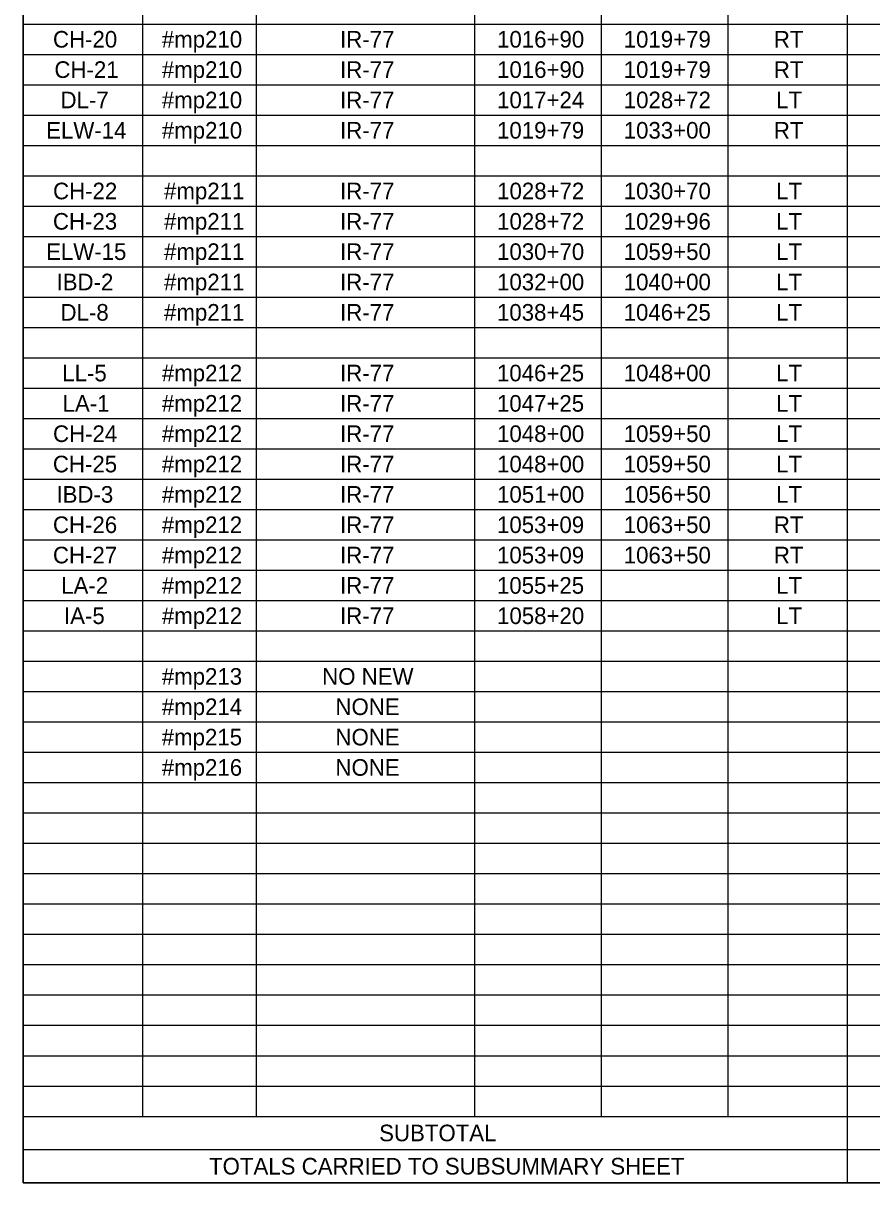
# Model space of a CAD drawing. Extents: x 91011267 to 91022583, y 37007614 to 37014266.
# Drawn here: x 91011277 to 91011662, y 37007614 to 37008139 of the extents above; entities that cross this region are included whole.
import ezdxf

# ---------------------------------------------------------------- set-up
doc = ezdxf.new("R2010")
doc.units = 0
doc.layers.add('SC_Scratch2', color=7, linetype='Continuous')
doc.layers.add('SH_Data', color=7, linetype='Continuous')

msp = doc.modelspace()

# ---------------------------------------------------------------- linework, layer by layer
at = {"layer": 'SC_Scratch2'}
msp.add_lwpolyline([(91011277.35, 37008663.81), (91012802.35, 37008663.81), (91012802.35, 37007613.81), (91011277.35, 37007613.81)], close=True, dxfattribs=at)
at = {"layer": 'SH_Data'}
for p, q in [((91011277.35, 37008289.61), (91011277.35, 37008083.53)), ((91011331.39, 37008289.61), (91011331.39, 37008083.53)), ((91011382.8, 37008289.61), (91011382.8, 37008083.53)), ((91011481.65, 37008289.61), (91011481.65, 37008083.53)), ((91011538.99, 37008289.61), (91011538.99, 37008083.53)), ((91011596.32, 37008289.61), (91011596.32, 37008083.53)), ((91011650.36, 37008289.61), (91011650.36, 37008083.53)), ((91011277.35, 37008138.48), (91011596.32, 37008138.48)), ((91011596.32, 37008138.48), (91011650.36, 37008138.48)), ((91011650.36, 37008138.48), (91011950.88, 37008138.48)), ((91011277.35, 37008124.75), (91011596.32, 37008124.75)), ((91011596.32, 37008124.75), (91011650.36, 37008124.75)), ((91011650.36, 37008124.75), (91011950.88, 37008124.75)), ((91011277.35, 37008111.01), (91011596.32, 37008111.01)), ((91011596.32, 37008111.01), (91011650.36, 37008111.01)), ((91011650.36, 37008111.01), (91011950.88, 37008111.01)), ((91011277.35, 37008097.27), (91011596.32, 37008097.27)), ((91011596.32, 37008097.27), (91011650.36, 37008097.27)), ((91011650.36, 37008097.27), (91011950.88, 37008097.27)), ((91011277.35, 37008083.53), (91011596.32, 37008083.53)), ((91011277.35, 37008083.53), (91011277.35, 37008069.79)), ((91011331.39, 37008083.53), (91011331.39, 37008069.79)), ((91011382.8, 37008083.53), (91011382.8, 37008069.79)), ((91011481.65, 37008083.53), (91011481.65, 37008069.79)), ((91011538.99, 37008083.53), (91011538.99, 37008069.79)), ((91011596.32, 37008083.53), (91011650.36, 37008083.53)), ((91011596.32, 37008083.53), (91011596.32, 37008069.79)), ((91011650.36, 37008083.53), (91011950.88, 37008083.53)), ((91011650.36, 37008083.53), (91011650.36, 37008069.79)), ((91011277.35, 37008069.79), (91011596.32, 37008069.79)), ((91011277.35, 37008069.79), (91011277.35, 37008056.05)), ((91011331.39, 37008069.79), (91011331.39, 37008056.05)), ((91011382.8, 37008069.79), (91011382.8, 37008056.05)), ((91011481.65, 37008069.79), (91011481.65, 37008056.05)), ((91011538.99, 37008069.79), (91011538.99, 37008056.05)), ((91011596.32, 37008069.79), (91011650.36, 37008069.79)), ((91011596.32, 37008069.79), (91011596.32, 37008056.05)), ((91011650.36, 37008069.79), (91011950.88, 37008069.79)), ((91011650.36, 37008069.79), (91011650.36, 37008056.05)), ((91011277.35, 37008056.05), (91011596.32, 37008056.05)), ((91011277.35, 37008056.05), (91011277.35, 37008014.84)), ((91011331.39, 37008056.05), (91011331.39, 37008014.84)), ((91011382.8, 37008056.05), (91011382.8, 37008014.84)), ((91011481.65, 37008056.05), (91011481.65, 37008014.84)), ((91011538.99, 37008056.05), (91011538.99, 37008014.84)), ((91011596.32, 37008056.05), (91011650.36, 37008056.05)), ((91011596.32, 37008056.05), (91011596.32, 37008014.84)), ((91011650.36, 37008056.05), (91011950.88, 37008056.05)), ((91011650.36, 37008056.05), (91011650.36, 37008014.84)), ((91011277.35, 37008042.32), (91011596.32, 37008042.32)), ((91011596.32, 37008042.32), (91011650.36, 37008042.32)), ((91011650.36, 37008042.32), (91011950.88, 37008042.32)), ((91011277.35, 37008028.58), (91011596.32, 37008028.58)), ((91011596.32, 37008028.58), (91011650.36, 37008028.58)), ((91011650.36, 37008028.58), (91011950.88, 37008028.58)), ((91011277.35, 37008014.84), (91011596.32, 37008014.84)), ((91011277.35, 37008014.84), (91011277.35, 37008001.1)), ((91011331.39, 37008014.84), (91011331.39, 37008001.1)), ((91011382.8, 37008014.84), (91011382.8, 37008001.1)), ((91011481.65, 37008014.84), (91011481.65, 37008001.1)), ((91011538.99, 37008014.84), (91011538.99, 37008001.1)), ((91011596.32, 37008014.84), (91011650.36, 37008014.84)), ((91011596.32, 37008014.84), (91011596.32, 37008001.1)), ((91011650.36, 37008014.84), (91011950.88, 37008014.84)), ((91011650.36, 37008014.84), (91011650.36, 37008001.1)), ((91011277.35, 37008001.1), (91011596.32, 37008001.1)), ((91011277.35, 37008001.1), (91011277.35, 37007987.36)), ((91011331.39, 37008001.1), (91011331.39, 37007987.36)), ((91011382.8, 37008001.1), (91011382.8, 37007987.36)), ((91011481.65, 37008001.1), (91011481.65, 37007987.36)), ((91011538.99, 37008001.1), (91011538.99, 37007987.36)), ((91011596.32, 37008001.1), (91011650.36, 37008001.1)), ((91011596.32, 37008001.1), (91011596.32, 37007987.36)), ((91011650.36, 37008001.1), (91011950.88, 37008001.1)), ((91011650.36, 37008001.1), (91011650.36, 37007987.36)), ((91011277.35, 37007987.36), (91011596.32, 37007987.36)), ((91011277.35, 37007987.36), (91011277.35, 37007946.15)), ((91011331.39, 37007987.36), (91011331.39, 37007946.15)), ((91011382.8, 37007987.36), (91011382.8, 37007946.15)), ((91011481.65, 37007987.36), (91011481.65, 37007946.15)), ((91011538.99, 37007987.36), (91011538.99, 37007946.15)), ((91011596.32, 37007987.36), (91011650.36, 37007987.36)), ((91011596.32, 37007987.36), (91011596.32, 37007946.15)), ((91011650.36, 37007987.36), (91011950.88, 37007987.36)), ((91011650.36, 37007987.36), (91011650.36, 37007946.15)), ((91011277.35, 37007973.62), (91011596.32, 37007973.62)), ((91011596.32, 37007973.62), (91011650.36, 37007973.62)), ((91011650.36, 37007973.62), (91011950.88, 37007973.62)), ((91011277.35, 37007959.89), (91011596.32, 37007959.89)), ((91011596.32, 37007959.89), (91011650.36, 37007959.89)), ((91011650.36, 37007959.89), (91011950.88, 37007959.89)), ((91011277.35, 37007946.15), (91011596.32, 37007946.15)), ((91011277.35, 37007946.15), (91011277.35, 37007932.41)), ((91011331.39, 37007946.15), (91011331.39, 37007932.41)), ((91011382.8, 37007946.15), (91011382.8, 37007932.41)), ((91011481.65, 37007946.15), (91011481.65, 37007932.41)), ((91011538.99, 37007946.15), (91011538.99, 37007932.41)), ((91011596.32, 37007946.15), (91011650.36, 37007946.15)), ((91011596.32, 37007946.15), (91011596.32, 37007932.41)), ((91011650.36, 37007946.15), (91011950.88, 37007946.15)), ((91011650.36, 37007946.15), (91011650.36, 37007932.41)), ((91011277.35, 37007932.41), (91011596.32, 37007932.41)), ((91011277.35, 37007932.41), (91011277.35, 37007918.67)), ((91011331.39, 37007932.41), (91011331.39, 37007918.67)), ((91011382.8, 37007932.41), (91011382.8, 37007918.67)), ((91011481.65, 37007932.41), (91011481.65, 37007918.67)), ((91011538.99, 37007932.41), (91011538.99, 37007918.67)), ((91011596.32, 37007932.41), (91011650.36, 37007932.41)), ((91011596.32, 37007932.41), (91011596.32, 37007918.67)), ((91011650.36, 37007932.41), (91011950.88, 37007932.41)), ((91011650.36, 37007932.41), (91011650.36, 37007918.67)), ((91011277.35, 37007918.67), (91011596.32, 37007918.67)), ((91011277.35, 37007918.67), (91011277.35, 37007613.81)), ((91011331.39, 37007918.67), (91011331.39, 37007643.9)), ((91011382.8, 37007918.67), (91011382.8, 37007643.9)), ((91011481.65, 37007918.67), (91011481.65, 37007643.9)), ((91011538.99, 37007918.67), (91011538.99, 37007643.9)), ((91011596.32, 37007918.67), (91011650.36, 37007918.67)), ((91011596.32, 37007918.67), (91011596.32, 37007643.9)), ((91011650.36, 37007918.67), (91011950.88, 37007918.67)), ((91011650.36, 37007918.67), (91011650.36, 37007613.81)), ((91011277.35, 37007904.93), (91011596.32, 37007904.93)), ((91011596.32, 37007904.93), (91011650.36, 37007904.93)), ((91011650.36, 37007904.93), (91011950.88, 37007904.93)), ((91011277.35, 37007891.19), (91011596.32, 37007891.19)), ((91011596.32, 37007891.19), (91011650.36, 37007891.19)), ((91011650.36, 37007891.19), (91011950.88, 37007891.19)), ((91011277.35, 37007877.46), (91011596.32, 37007877.46)), ((91011596.32, 37007877.46), (91011650.36, 37007877.46)), ((91011650.36, 37007877.46), (91011950.88, 37007877.46)), ((91011277.35, 37007863.72), (91011596.32, 37007863.72)), ((91011596.32, 37007863.72), (91011650.36, 37007863.72)), ((91011650.36, 37007863.72), (91011950.88, 37007863.72)), ((91011277.35, 37007849.98), (91011596.32, 37007849.98)), ((91011596.32, 37007849.98), (91011650.36, 37007849.98)), ((91011650.36, 37007849.98), (91011950.88, 37007849.98)), ((91011277.35, 37007836.24), (91011596.32, 37007836.24)), ((91011596.32, 37007836.24), (91011650.36, 37007836.24)), ((91011650.36, 37007836.24), (91011950.88, 37007836.24)), ((91011277.35, 37007822.5), (91011596.32, 37007822.5)), ((91011596.32, 37007822.5), (91011650.36, 37007822.5)), ((91011650.36, 37007822.5), (91011950.88, 37007822.5)), ((91011277.35, 37007808.76), (91011596.32, 37007808.76)), ((91011596.32, 37007808.76), (91011650.36, 37007808.76)), ((91011650.36, 37007808.76), (91011950.88, 37007808.76)), ((91011277.35, 37007795.03), (91011596.32, 37007795.03)), ((91011596.32, 37007795.03), (91011650.36, 37007795.03)), ((91011650.36, 37007795.03), (91011950.88, 37007795.03)), ((91011277.35, 37007781.29), (91011596.32, 37007781.29)), ((91011596.32, 37007781.29), (91011650.36, 37007781.29)), ((91011650.36, 37007781.29), (91011950.88, 37007781.29)), ((91011277.35, 37007767.55), (91011596.32, 37007767.55)), ((91011596.32, 37007767.55), (91011650.36, 37007767.55)), ((91011650.36, 37007767.55), (91011950.88, 37007767.55)), ((91011277.35, 37007753.81), (91011596.32, 37007753.81)), ((91011596.32, 37007753.81), (91011650.36, 37007753.81)), ((91011650.36, 37007753.81), (91011950.88, 37007753.81)), ((91011277.35, 37007740.07), (91011596.32, 37007740.07)), ((91011596.32, 37007740.07), (91011650.36, 37007740.07)), ((91011650.36, 37007740.07), (91011950.88, 37007740.07)), ((91011277.35, 37007726.33), (91011596.32, 37007726.33)), ((91011596.32, 37007726.33), (91011650.36, 37007726.33)), ((91011650.36, 37007726.33), (91011950.88, 37007726.33)), ((91011277.35, 37007712.6), (91011596.32, 37007712.6)), ((91011596.32, 37007712.6), (91011650.36, 37007712.6)), ((91011650.36, 37007712.6), (91011950.88, 37007712.6)), ((91011277.35, 37007698.86), (91011596.32, 37007698.86)), ((91011596.32, 37007698.86), (91011650.36, 37007698.86)), ((91011650.36, 37007698.86), (91011950.88, 37007698.86)), ((91011277.35, 37007685.12), (91011596.32, 37007685.12)), ((91011596.32, 37007685.12), (91011650.36, 37007685.12)), ((91011650.36, 37007685.12), (91011950.88, 37007685.12)), ((91011277.35, 37007671.38), (91011596.32, 37007671.38)), ((91011596.32, 37007671.38), (91011650.36, 37007671.38)), ((91011650.36, 37007671.38), (91011950.88, 37007671.38)), ((91011277.35, 37007657.64), (91011596.32, 37007657.64)), ((91011596.32, 37007657.64), (91011650.36, 37007657.64)), ((91011650.36, 37007657.64), (91011950.88, 37007657.64)), ((91011277.35, 37007643.9), (91011596.32, 37007643.9)), ((91011596.32, 37007643.9), (91011650.36, 37007643.9)), ((91011650.36, 37007643.9), (91011950.88, 37007643.9)), ((91011277.35, 37007628.86), (91011596.32, 37007628.86)), ((91011596.32, 37007628.86), (91011650.36, 37007628.86)), ((91011650.36, 37007628.86), (91011950.88, 37007628.86)), ((91011277.35, 37007613.81), (91011596.32, 37007613.81)), ((91011596.32, 37007613.81), (91011650.36, 37007613.81)), ((91011650.36, 37007613.81), (91011950.88, 37007613.81))]:
    msp.add_line(p, q, dxfattribs=at)

# ---------------------------------------------------------------- texts
for s, height, p in [('CH-20', 7.523, (91011290.83, 37008127.85)), ('#mp210', 7.523, (91011340.11, 37008127.85)), ('IR-77', 7.523, (91011420.79, 37008127.85)), ('1016+90', 7.523, (91011491.87, 37008127.85)), ('1019+79', 7.523, (91011549.19, 37008127.85)), ('RT', 7.523, (91011617.17, 37008127.85)), ('CH-21', 7.523, (91011291.48, 37008114.12)), ('#mp210', 7.523, (91011340.11, 37008114.12)), ('IR-77', 7.523, (91011420.79, 37008114.12)), ('1016+90', 7.523, (91011491.87, 37008114.12)), ('1019+79', 7.523, (91011549.19, 37008114.12)), ('RT', 7.523, (91011617.17, 37008114.12)), ('DL-7', 7.523, (91011294.26, 37008100.38)), ('#mp210', 7.523, (91011340.11, 37008100.38)), ('IR-77', 7.523, (91011420.79, 37008100.38)), ('1017+24', 7.523, (91011491.87, 37008100.38)), ('1028+72', 7.523, (91011549.23, 37008100.38)), ('LT', 7.523, (91011618.23, 37008100.38)), ('ELW-14', 7.523, (91011287.75, 37008086.64)), ('#mp210', 7.523, (91011340.11, 37008086.64)), ('IR-77', 7.523, (91011420.79, 37008086.64)), ('1019+79', 7.523, (91011491.85, 37008086.64)), ('1033+00', 7.523, (91011549.21, 37008086.64)), ('RT', 7.523, (91011617.17, 37008086.64)), ('CH-22', 7.523, (91011290.86, 37008059.16)), ('#mp211', 7.523, (91011341.11, 37008059.16)), ('IR-77', 7.523, (91011420.79, 37008059.16)), ('1028+72', 7.523, (91011491.9, 37008059.16)), ('1030+70', 7.523, (91011549.21, 37008059.16)), ('LT', 7.523, (91011618.23, 37008059.16)), ('CH-23', 7.523, (91011290.82, 37008045.42)), ('#mp211', 7.523, (91011341.11, 37008045.42)), ('IR-77', 7.523, (91011420.79, 37008045.42)), ('1028+72', 7.523, (91011491.9, 37008045.42)), ('1029+96', 7.523, (91011549.2, 37008045.42)), ('LT', 7.523, (91011618.23, 37008045.42)), ('ELW-15', 7.523, (91011287.71, 37008031.69)), ('#mp211', 7.523, (91011341.11, 37008031.69)), ('IR-77', 7.523, (91011420.79, 37008031.69)), ('1030+70', 7.523, (91011491.87, 37008031.69)), ('1059+50', 7.523, (91011549.21, 37008031.69)), ('LT', 7.523, (91011618.23, 37008031.69)), ('IBD-2', 7.523, (91011292.44, 37008017.95)), ('#mp211', 7.523, (91011341.11, 37008017.95)), ('IR-77', 7.523, (91011420.79, 37008017.95)), ('1032+00', 7.523, (91011491.87, 37008017.95)), ('1040+00', 7.523, (91011549.21, 37008017.95)), ('LT', 7.523, (91011618.23, 37008017.95)), ('DL-8', 7.523, (91011294.26, 37008004.21)), ('#mp211', 7.523, (91011341.11, 37008004.21)), ('IR-77', 7.523, (91011420.79, 37008004.21)), ('1038+45', 7.523, (91011491.83, 37008004.21)), ('1046+25', 7.523, (91011549.17, 37008004.21)), ('LT', 7.523, (91011618.23, 37008004.21)), ('LL-5', 7.523, (91011295.03, 37007976.73)), ('#mp212', 7.523, (91011340.13, 37007976.73)), ('IR-77', 7.523, (91011420.79, 37007976.73)), ('1046+25', 7.523, (91011491.83, 37007976.73)), ('1048+00', 7.523, (91011549.21, 37007976.73)), ('LT', 7.523, (91011618.23, 37007976.73)), ('LA-1', 7.523, (91011295.18, 37007962.99)), ('#mp212', 7.523, (91011340.13, 37007962.99)), ('IR-77', 7.523, (91011420.79, 37007962.99)), ('1047+25', 7.523, (91011491.83, 37007962.99)), ('LT', 7.523, (91011618.23, 37007962.99)), ('CH-24', 7.523, (91011290.84, 37007949.26)), ('#mp212', 7.523, (91011340.13, 37007949.26)), ('IR-77', 7.523, (91011420.79, 37007949.26)), ('1048+00', 7.523, (91011491.87, 37007949.26)), ('1059+50', 7.523, (91011549.21, 37007949.26)), ('LT', 7.523, (91011618.23, 37007949.26)), ('CH-25', 7.523, (91011290.79, 37007935.52)), ('#mp212', 7.523, (91011340.13, 37007935.52)), ('IR-77', 7.523, (91011420.79, 37007935.52)), ('1048+00', 7.523, (91011491.87, 37007935.52)), ('1059+50', 7.523, (91011549.21, 37007935.52)), ('LT', 7.523, (91011618.23, 37007935.52)), ('IBD-3', 7.523, (91011292.41, 37007921.78)), ('#mp212', 7.523, (91011340.13, 37007921.78)), ('IR-77', 7.523, (91011420.79, 37007921.78)), ('1051+00', 7.523, (91011491.87, 37007921.78)), ('1056+50', 7.523, (91011549.21, 37007921.78)), ('LT', 7.523, (91011618.23, 37007921.78)), ('CH-26', 7.523, (91011290.82, 37007908.04)), ('#mp212', 7.523, (91011340.13, 37007908.04)), ('IR-77', 7.523, (91011420.79, 37007908.04)), ('1053+09', 7.523, (91011491.85, 37007908.04)), ('1063+50', 7.523, (91011549.21, 37007908.04)), ('RT', 7.523, (91011617.17, 37007908.04)), ('CH-27', 7.523, (91011290.82, 37007894.3)), ('#mp212', 7.523, (91011340.13, 37007894.3)), ('IR-77', 7.523, (91011420.79, 37007894.3)), ('1053+09', 7.523, (91011491.85, 37007894.3)), ('1063+50', 7.523, (91011549.21, 37007894.3)), ('RT', 7.523, (91011617.17, 37007894.3)), ('LA-2', 7.523, (91011294.56, 37007880.56)), ('#mp212', 7.523, (91011340.13, 37007880.56)), ('IR-77', 7.523, (91011420.79, 37007880.56)), ('1055+25', 7.523, (91011491.83, 37007880.56)), ('LT', 7.523, (91011618.23, 37007880.56)), ('#mp212', 7.523, (91011340.13, 37007866.83)), ('1058+20', 7.523, (91011491.87, 37007866.83)), ('IA-5', 7.523, (91011295.82, 37007866.83)), ('IR-77', 7.523, (91011420.79, 37007866.83)), ('LT', 7.523, (91011618.23, 37007866.83)), ('#mp213', 7.523, (91011340.1, 37007839.35)), ('NO NEW', 7.523, (91011412.69, 37007839.35)), ('#mp214', 7.523, (91011340.11, 37007825.61)), ('NONE', 7.523, (91011418.71, 37007825.61)), ('#mp215', 7.523, (91011340.07, 37007811.87)), ('NONE', 7.523, (91011418.71, 37007811.87)), ('#mp216', 7.523, (91011340.1, 37007798.13)), ('NONE', 7.523, (91011418.71, 37007798.13)), ('SUBTOTAL', 7.523, (91011438.49, 37007632.62)), ('TOTALS CARRIED TO SUBSUMMARY SHEET', 7.5234, (91011361.48, 37007617.57))]:
    msp.add_text(s, height=height, dxfattribs=at).set_placement(p)

doc.saveas('drawing.dxf')
